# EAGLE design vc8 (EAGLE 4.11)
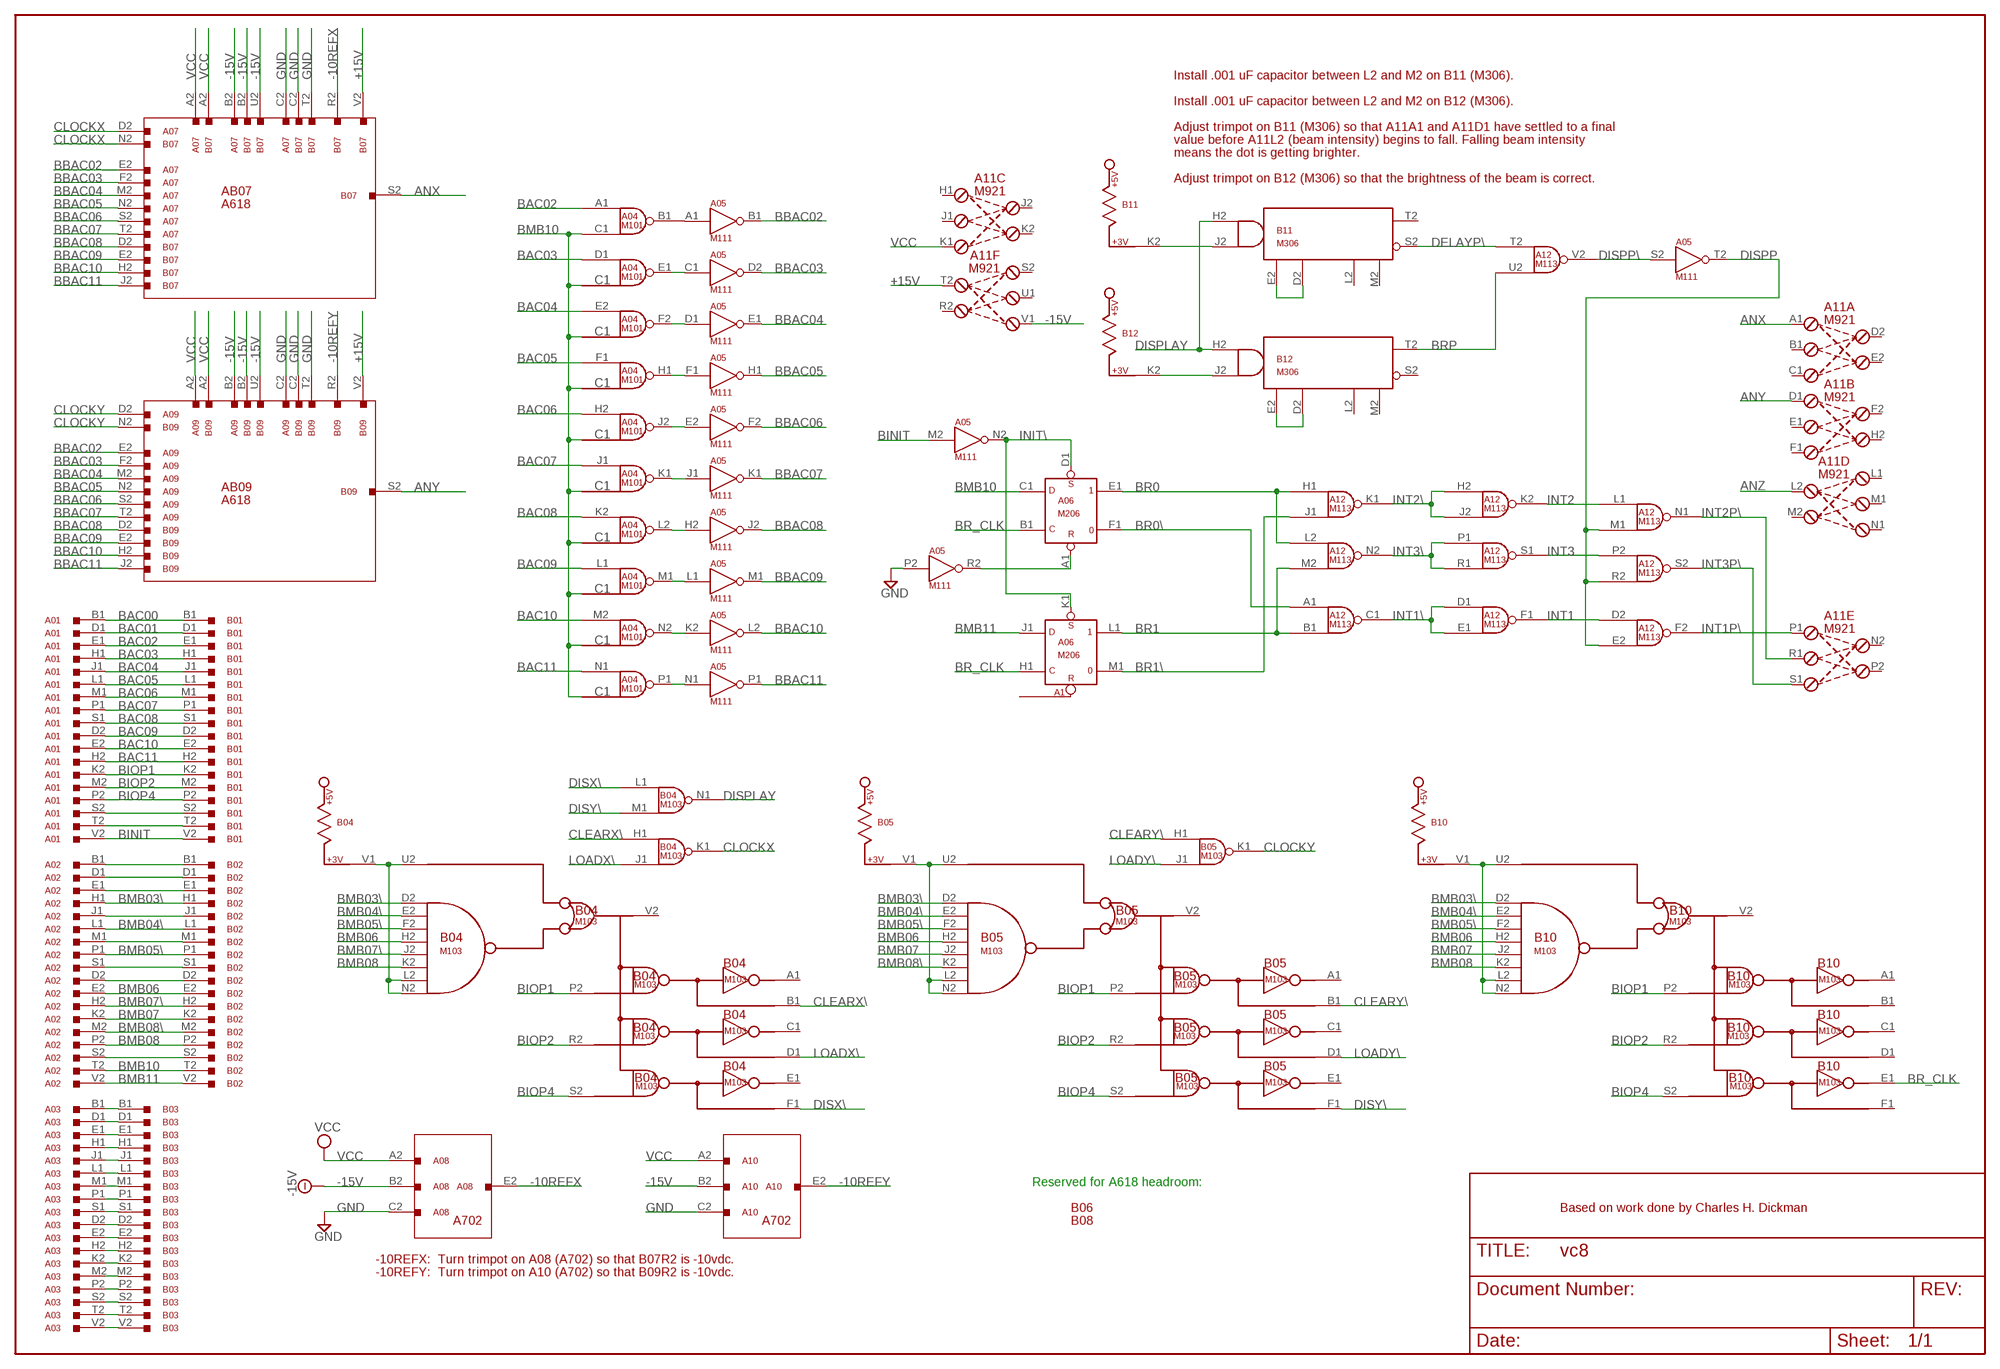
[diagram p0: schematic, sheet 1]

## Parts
A01  M903  [H807]
A02  M903  [H807]
A03  M903  [H807]
A04  M101  [H807]
A05  M111  [H807]
A06  M206  M206X  [H807]
A07  A618A  M916  [H807]
A08  A702  M916  [H807]
A09  A618A  M916  [H807]
A10  A702  M916  [H807]
A11  M921  [H807]
A12  M113  [H807]
B01  M903  [H807]
B02  M903  [H807]
B03  M903  [H807]
B04  M103  [H807]
B05  M103  [H807]
B06  EMPTY  [H807]
B07  A618B  M916  [H807]
B08  EMPTY  [H807]
B09  A618B  M916  [H807]
B10  M103  [H807]
B11  M306  [H807]
B12  M306  [H807]

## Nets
+3VB04: B04.L2(V2:L2) B04.N2(V2:N2) B04.U2(V2:U2) B04.V1
+3VB05: B05.L2(V2:L2) B05.N2(V2:N2) B05.U2(V2:U2) B05.V1
+3VB10: B10.L2(V2:L2) B10.N2(V2:N2) B10.U2(V2:U2) B10.V1
+15V: A11.T2(F:R1) B07.V2 B09.V2
-10REFX: A08.E2 B07.R2
-10REFY: A10.E2 B09.R2
-15V: A07.B2 A08.B2 A09.B2 A10.B2 A11.V1(F:L3) B07.B2 B07.U2 B09.B2 B09.U2
ANX: A11.A1(A:L1) B07.S2
ANY: A11.D1(B:L1) B09.S2
ANZ: A11.L2(D:R1)
BAC00: A01.B1 B01.B1
BAC01: A01.D1 B01.D1
BAC02: A01.E1 A04.A1(B1:IN1) B01.E1
BAC03: A01.H1 A04.D1(E1:IN) B01.H1
BAC04: A01.J1 A04.E2(F2:IN) B01.J1
BAC05: A01.L1 A04.F1(H1:IN) B01.L1
BAC06: A01.M1 A04.H2(J2:IN) B01.M1
BAC07: A01.P1 A04.J1(K1:IN) B01.P1
BAC08: A01.S1 A04.K2(L2:IN) B01.S1
BAC09: A01.D2 A04.L1(M1:IN) B01.D2
BAC10: A01.E2 A04.M2(N2:IN) B01.E2
BAC11: A01.H2 A04.N1(P1:IN) B01.H2
BBAC02: A05.B1(B1:OUT) A07.E2 A09.E2
BBAC03: A05.D2(D2:OUT) A07.F2 A09.F2
BBAC04: A05.E1(E1:OUT) A07.M2 A09.M2
BBAC05: A05.H1(H1:OUT) A07.N2 A09.N2
BBAC06: A05.F2(F2:OUT) A07.S2 A09.S2
BBAC07: A05.K1(K1:OUT) A07.T2 A09.T2
BBAC08: A05.J2(J2:OUT) B07.D2 B09.D2
BBAC09: A05.M1(M1:OUT) B07.E2 B09.E2
BBAC10: A05.L2(L2:OUT) B07.H2 B09.H2
BBAC11: A05.P1(P1:OUT) B07.J2 B09.J2
BINIT: A01.V2 A05.M2(N2:IN) B01.V2
BIOP1: A01.K2 B01.K2 B04.P2(V2:P2) B05.P2(V2:P2) B10.P2(V2:P2)
BIOP2: A01.M2 B01.M2 B04.R2(V2:R2) B05.R2(V2:R2) B10.R2(V2:R2)
BIOP4: A01.P2 B01.P2 B04.S2(V2:S2) B05.S2(V2:S2) B10.S2(V2:S2)
BMB03\: A02.H1 B02.H1 B04.D2(V2:D2) B05.D2(V2:D2) B10.D2(V2:D2)
BMB04\: A02.L1 B02.L1 B04.E2(V2:E2) B05.E2(V2:E2) B10.E2(V2:E2)
BMB05\: A02.P1 B02.P1 B04.F2(V2:F2) B05.F2(V2:F2) B10.F2(V2:F2)
BMB06: A02.E2 B02.E2 B04.H2(V2:H2) B05.H2(V2:H2) B10.H2(V2:H2)
BMB07: A02.K2 B02.K2 B05.J2(V2:J2) B10.J2(V2:J2)
BMB07\: A02.H2 B02.H2 B04.J2(V2:J2)
BMB08: A02.P2 B02.P2 B04.K2(V2:K2) B10.K2(V2:K2)
BMB08\: A02.M2 B02.M2 B05.K2(V2:K2)
BMB10: A02.T2 A04.C1(B1:IN2) A06.C1(E1:D) B02.T2
BMB11: A02.V2 A06.J1(L1:D) B02.V2
BR0: A06.E1 A12.H1(K1:IN1) A12.L2(N2:IN1)
BR0\: A06.F1 A12.A1(C1:IN1)
BR1: A06.L1 A12.B1(C1:IN2) A12.M2(N2:IN2)
BR1\: A06.M1 A12.J1(K1:IN2)
BR_CLK: A06.B1(E1:C) A06.H1(L1:C) B10.E1(V2:E1)
BRP: A12.U2(V2:IN2) B12.T2(T)
CLEARX\: B04.B1(V2:B1) B04.H1(K1:IN1)
CLEARY\: B05.B1(V2:B1) B05.H1(K1:IN1)
CLOCKX: A07.D2 B04.K1(K1:OUT) B07.N2
CLOCKY: A09.D2 B05.K1(K1:OUT) B09.N2
DELAYP\: A12.T2(V2:IN1) B11.S2(S)
DISPLAY: B04.N1(N1:OUT) B11.H2(H) B12.H2(H)
DISPP: A05.T2(T2:OUT) A12.E2(F2:IN2) A12.M1(N1:IN2) A12.R2(S2:IN2)
DISPP\: A05.S2(T2:IN) A12.V2(V2:OUT)
DISX\: B04.F1(V2:F1) B04.L1(N1:IN1)
DISY\: B04.M1(N1:IN2) B05.F1(V2:F1)
GND: A05.P2(R2:IN) A07.C2 A08.C2 A09.C2 A10.C2 B07.C2 B07.T2 B09.C2 B09.T2
INIT\: A05.N2(N2:OUT) A06.D1(E1:S) A06.K1(L1:S)
INT1: A12.D2(F2:IN1) A12.F1(F1:OUT)
INT1\: A12.C1(C1:OUT) A12.D1(F1:IN1) A12.E1(F1:IN2)
INT1P\: A11.P1(E:L1) A12.F2(F2:OUT)
INT2: A12.K2(K2:OUT) A12.L1(N1:IN1)
INT2\: A12.H2(K2:IN1) A12.J2(K2:IN2) A12.K1(K1:OUT)
INT2P\: A11.R1(E:L2) A12.N1(N1:OUT)
INT3: A12.P2(S2:IN1) A12.S1(S1:OUT)
INT3\: A12.N2(N2:OUT) A12.P1(S1:IN1) A12.R1(S1:IN2)
INT3P\: A11.S1(E:L3) A12.S2(S2:OUT)
LOADX\: B04.D1(V2:D1) B04.J1(K1:IN2)
LOADY\: B05.D1(V2:D1) B05.J1(K1:IN2)
N$1: A05.R2(R2:OUT) A06.A1(E1:R)
N$2: B11.J2(J) B11.K2
N$4: B12.J2(J) B12.K2
N$6: B11.D2(D) B11.E2(E)
N$7: B12.D2(D) B12.E2(E)
N$9: A04.B1(B1:OUT) A05.A1(B1:IN)
N$10: A04.E1(E1:OUT) A05.C1(D2:IN)
N$11: A04.F2(F2:OUT) A05.D1(E1:IN)
N$12: A04.H1(H1:OUT) A05.F1(H1:IN)
N$13: A04.J2(J2:OUT) A05.E2(F2:IN)
N$14: A04.P1(P1:OUT) A05.N1(P1:IN)
N$15: A04.N2(N2:OUT) A05.K2(L2:IN)
N$16: A04.M1(M1:OUT) A05.L1(M1:IN)
N$17: A04.L2(L2:OUT) A05.H2(J2:IN)
N$18: A04.K1(K1:OUT) A05.J1(K1:IN)
N$21: A03.B1 B03.B1
N$22: A03.D1 B03.D1
N$23: A03.E1 B03.E1
N$24: A03.H1 B03.H1
N$26: A03.J1 B03.J1
N$27: A03.L1 B03.L1
N$28: A03.M1 B03.M1
N$29: A03.P1 B03.P1
N$30: A03.S1 B03.S1
N$33: A03.D2 B03.D2
N$34: A03.E2 B03.E2
N$35: A03.H2 B03.H2
N$36: A03.K2 B03.K2
N$37: A03.M2 B03.M2
N$38: A03.P2 B03.P2
N$39: A03.S2 B03.S2
N$40: A03.T2 B03.T2
N$41: A03.V2 B03.V2
N$42: A02.D2 B02.D2
N$43: A02.S1 B02.S1
N$44: A02.J1 B02.J1
N$45: A02.M1 B02.M1
N$46: A02.S2 B02.S2
N$47: A02.B1 B02.B1
N$48: A02.D1 B02.D1
N$49: A02.E1 B02.E1
N$50: A01.T2 B01.T2
N$51: A01.S2 B01.S2
VCC: A07.A2 A08.A2 A09.A2 A10.A2 A11.K1(C:L3) B07.A2 B09.A2
Unconnected: A04.P2(R2:IN) A04.R1(S1:IN) A04.R2(R2:OUT) A04.S1(S1:OUT) A04.S2(T2:IN) A04.T2(T2:OUT) A04.U1(U1:OUT) A04.U2(V2:IN) A04.V1(U1:IN) A04.V2(V2:OUT) A05.R1(S1:IN) A05.S1(S1:OUT) A05.U1(U1:OUT) A05.U2(V2:IN) A05.V1(U1:IN) A05.V2(V2:OUT) A06.D2(H2:C) A06.E2(H2:D) A06.F2(H2:S) A06.H2 A06.J2 A06.K2(P2:R) A06.L2(P2:C) A06.M2(P2:D) A06.N1(S1:C) A06.N2(P2:S) A06.P1(S1:D) A06.P2 A06.R1(S1:S) A06.R2 A06.S1 A06.S2(V2:C) A06.T2(V2:D) A06.U1 A06.U2(V2:S) A06.V1 A06.V2 A07.A1 A07.B1 A07.C1 A07.D1 A07.E1 A07.F1 A07.H1 A07.H2 A07.J1 A07.J2 A07.K1 A07.K2 A07.L1 A07.L2 A07.M1 A07.N1 A07.P1 A07.P2 A07.R1 A07.R2 A07.S1 A07.T1 A07.U1 A07.U2 A07.V1 A07.V2 A08.A1 A08.B1 A08.C1 A08.D1 A08.D2 A08.E1 A08.F1 A08.F2 A08.H1 A08.H2 A08.J1 A08.J2 A08.K1 A08.K2 A08.L1 A08.L2 A08.M1 A08.M2 A08.N1 A08.N2 A08.P1 A08.P2 A08.R1 A08.R2 A08.S1 A08.S2 A08.T1 A08.T2 A08.U1 A08.U2 A08.V1 A08.V2 A09.A1 A09.B1 A09.C1 A09.D1 A09.E1 A09.F1 A09.H1 A09.H2 A09.J1 A09.J2 A09.K1 A09.K2 A09.L1 A09.L2 A09.M1 A09.N1 A09.P1 A09.P2 A09.R1 A09.R2 A09.S1 A09.T1 A09.U1 A09.U2 A09.V1 A09.V2 A10.A1 A10.B1 A10.C1 A10.D1 A10.D2 A10.E1 A10.F1 A10.F2 A10.H1 A10.H2 A10.J1 A10.J2 A10.K1 A10.K2 A10.L1 A10.L2 A10.M1 A10.M2 A10.N1 A10.N2 A10.P1 A10.P2 A10.R1 A10.R2 A10.S1 A10.S2 A10.T1 A10.T2 A10.U1 A10.U2 A10.V1 A10.V2 A11.B1(A:L2) A11.C1(A:L3) A11.D2(A:R1) A11.E1(B:L2) A11.E2(A:R2) A11.F1(B:L3) A11.F2(B:R1) A11.H1(C:L1) A11.H2(B:R2) A11.J1(C:L2) A11.J2(C:R1) A11.K2(C:R2) A11.L1(D:L1) A11.M1(D:L2) A11.M2(D:R2) A11.N1(D:L3) A11.N2(E:R1) A11.P2(E:R2) A11.R2(F:R2) A11.S2(F:L1) A11.U1(F:L2) A12.U1 A12.V1 B04.A1(V2:A1) B04.C1(V2:C1) B04.E1(V2:E1) B04.V2(V2:V2) B05.A1(V2:A1) B05.C1(V2:C1) B05.E1(V2:E1) B05.L1(N1:IN1) B05.M1(N1:IN2) B05.N1(N1:OUT) B05.V2(V2:V2) B07.A1 B07.B1 B07.C1 B07.D1 B07.E1 B07.F1 B07.F2 B07.H1 B07.J1 B07.K1 B07.K2 B07.L1 B07.L2 B07.M1 B07.M2 B07.N1 B07.P1 B07.P2 B07.R1 B07.S1 B07.T1 B07.U1 B07.V1 B09.A1 B09.B1 B09.C1 B09.D1 B09.E1 B09.F1 B09.F2 B09.H1 B09.J1 B09.K1 B09.K2 B09.L1 B09.L2 B09.M1 B09.M2 B09.N1 B09.P1 B09.P2 B09.R1 B09.S1 B09.T1 B09.U1 B09.V1 B10.A1(V2:A1) B10.B1(V2:B1) B10.C1(V2:C1) B10.D1(V2:D1) B10.F1(V2:F1) B10.H1(K1:IN1) B10.J1(K1:IN2) B10.K1(K1:OUT) B10.L1(N1:IN1) B10.M1(N1:IN2) B10.N1(N1:OUT) B10.V2(V2:V2) B11.L2(L) B11.M2(M) B11.T2(T) B12.L2(L) B12.M2(M) B12.S2(S)

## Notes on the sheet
- Install .001 uF capacitor between L2 and M2 on B11 (M306).
- Install .001 uF capacitor between L2 and M2 on B12 (M306).
- Adjust trimpot on B11 (M306) so that A11A1 and A11D1 have settled to a final
- value before A11L2 (beam intensity) begins to fall. Falling beam intensity
- means the dot is getting brighter.
- Adjust trimpot on B12 (M306) so that the brightness of the beam is correct.
- AB07
- A618
- AB09
- A618
- Reserved for A618 headroom:
- Based on work done by Charles H. Dickman
- A702 | A702
- -10REFX:  Turn trimpot on A08 (A702) so that B07R2 is -10vdc.
- -10REFY:  Turn trimpot on A10 (A702) so that B09R2 is -10vdc.

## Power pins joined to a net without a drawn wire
-15V: B06.B2 B08.B2
GND: A01.A1 A01.C1 A01.C2 A01.F1 A01.F2 A01.J2 A01.K1 A01.L2 A01.N1 A01.N2 A01.R1 A01.R2 A01.T1 A01.U2 A02.A1 A02.C1 A02.C2 A02.F1 A02.F2 A02.J2 A02.K1 A02.L2 A02.N1 A02.N2 A02.R1 A02.R2 A02.T1 A02.U2 A03.A1 A03.C1 A03.C2 A03.F1 A03.F2 A03.J2 A03.K1 A03.L2 A03.N1 A03.N2 A03.R1 A03.R2 A03.T1 A03.U2 A04.C2(GND) A04.T1(GND) A05.C2(GND) A05.T1(GND) A06.C2(GND) A06.T1(GND) A12.C2(GND) A12.T1(GND) B01.A1 B01.C1 B01.C2 B01.F1 B01.F2 B01.J2 B01.K1 B01.L2 B01.N1 B01.N2 B01.R1 B01.R2 B01.T1 B01.U2 B02.A1 B02.C1 B02.C2 B02.F1 B02.F2 B02.J2 B02.K1 B02.L2 B02.N1 B02.N2 B02.R1 B02.R2 B02.T1 B02.U2 B03.A1 B03.C1 B03.C2 B03.F1 B03.F2 B03.J2 B03.K1 B03.L2 B03.N1 B03.N2 B03.R1 B03.R2 B03.T1 B03.U2 B04.C2(GND) B04.T1(GND) B05.C2(GND) B05.T1(GND) B06.C2 B08.C2 B10.C2(GND) B10.T1(GND) B11.C2(GND) B12.C2(GND)
VCC: A04.A2(VCC) A05.A2(VCC) A06.A2(VCC) A12.A2(VCC) B04.A2(VCC) B05.A2(VCC) B06.A2 B08.A2 B10.A2(VCC) B11.A2(VCC) B12.A2(VCC)

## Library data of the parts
A01-A03 B01-B03 = dec-m:M903: Two-sided Posibus cable/connector.
A04 = dec-r:M101: Bus Data Interface The M101 contains 15 two-input NAND gates. One input of each gate is tied to a common line so that all data signals can be enabled simultaneously. Each data signal presents one TTL load. The common input presents 15 loads. Each output can drive 10 loads. Power: 5V@82ma (max.)
A05 = dec-r:M111: Sixteen inverters.
A06 = dec-r:M206X: Two sets of 3 D flip-flops
A07-A09 A10 B07 B09 = dec-r:M916: Simple 36 pin connector/wire cable
A11 = dec-r:M921: Device Code Select Jumper Board
A12 = dec-r:M113: 10 2-input NAND Gates
B04 B05 B10 = dec-r:M103: M103 Device Selector Used to decode IOT requests.
B06 B08 = dec-r:EMPTY: Empty Slot
B11 B12 = dec-r:M306: M306 Integrating One-Shot

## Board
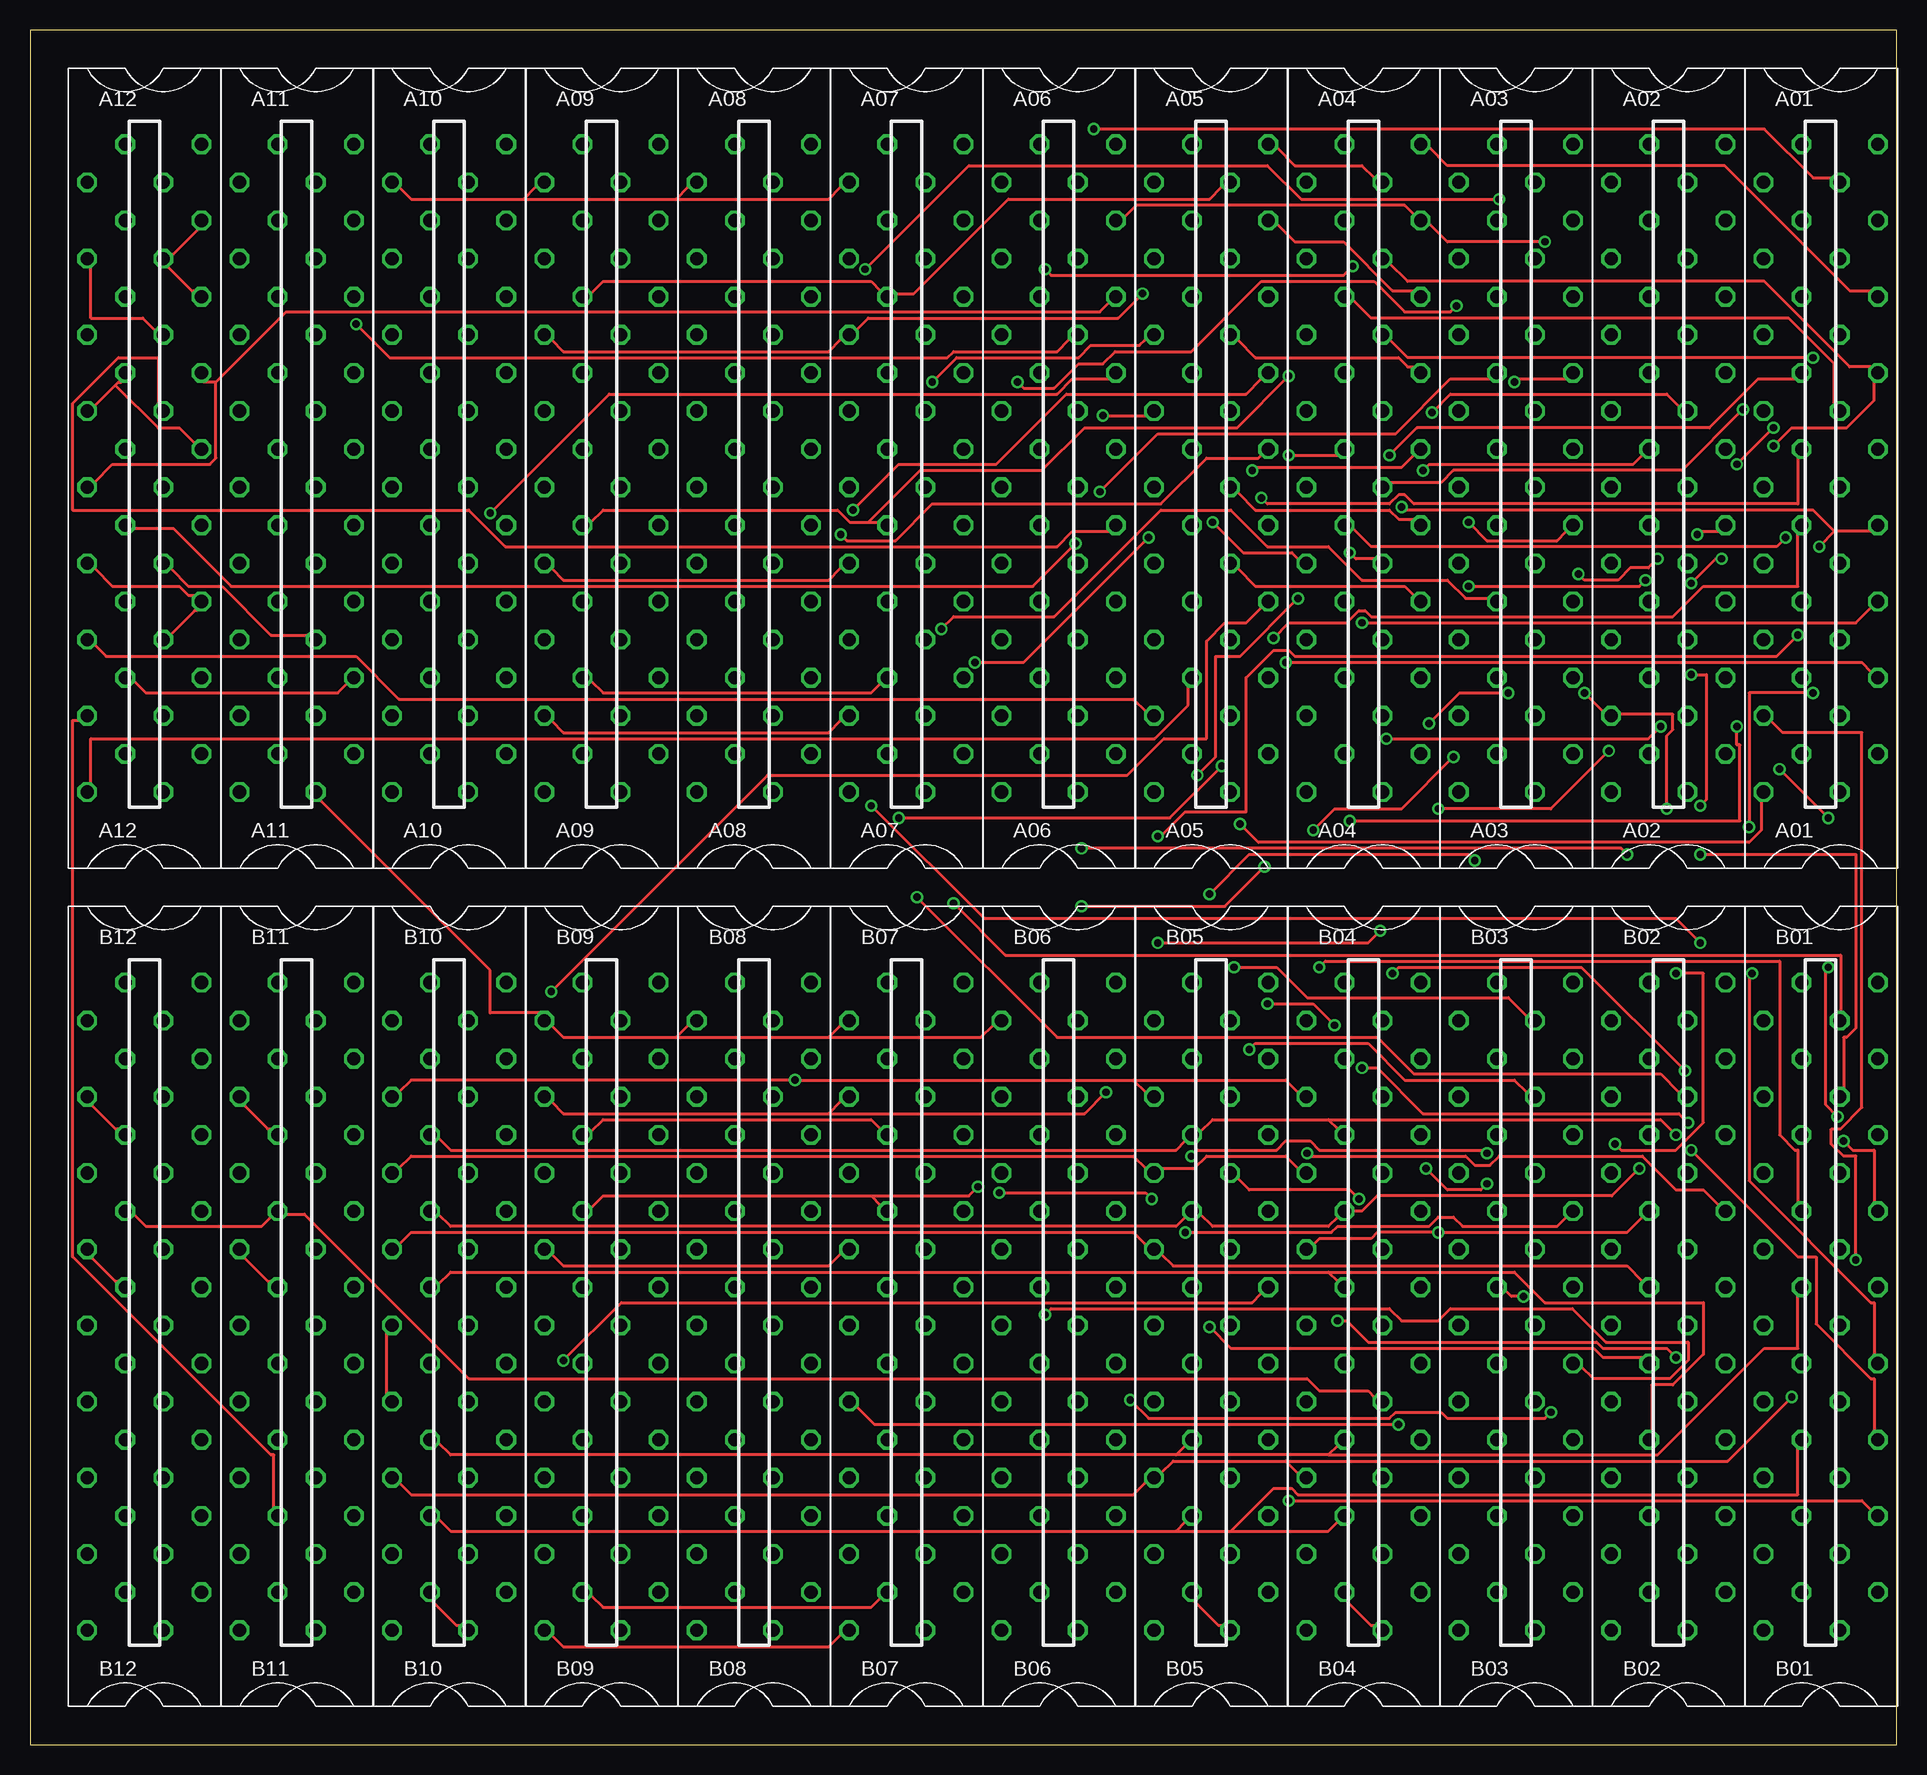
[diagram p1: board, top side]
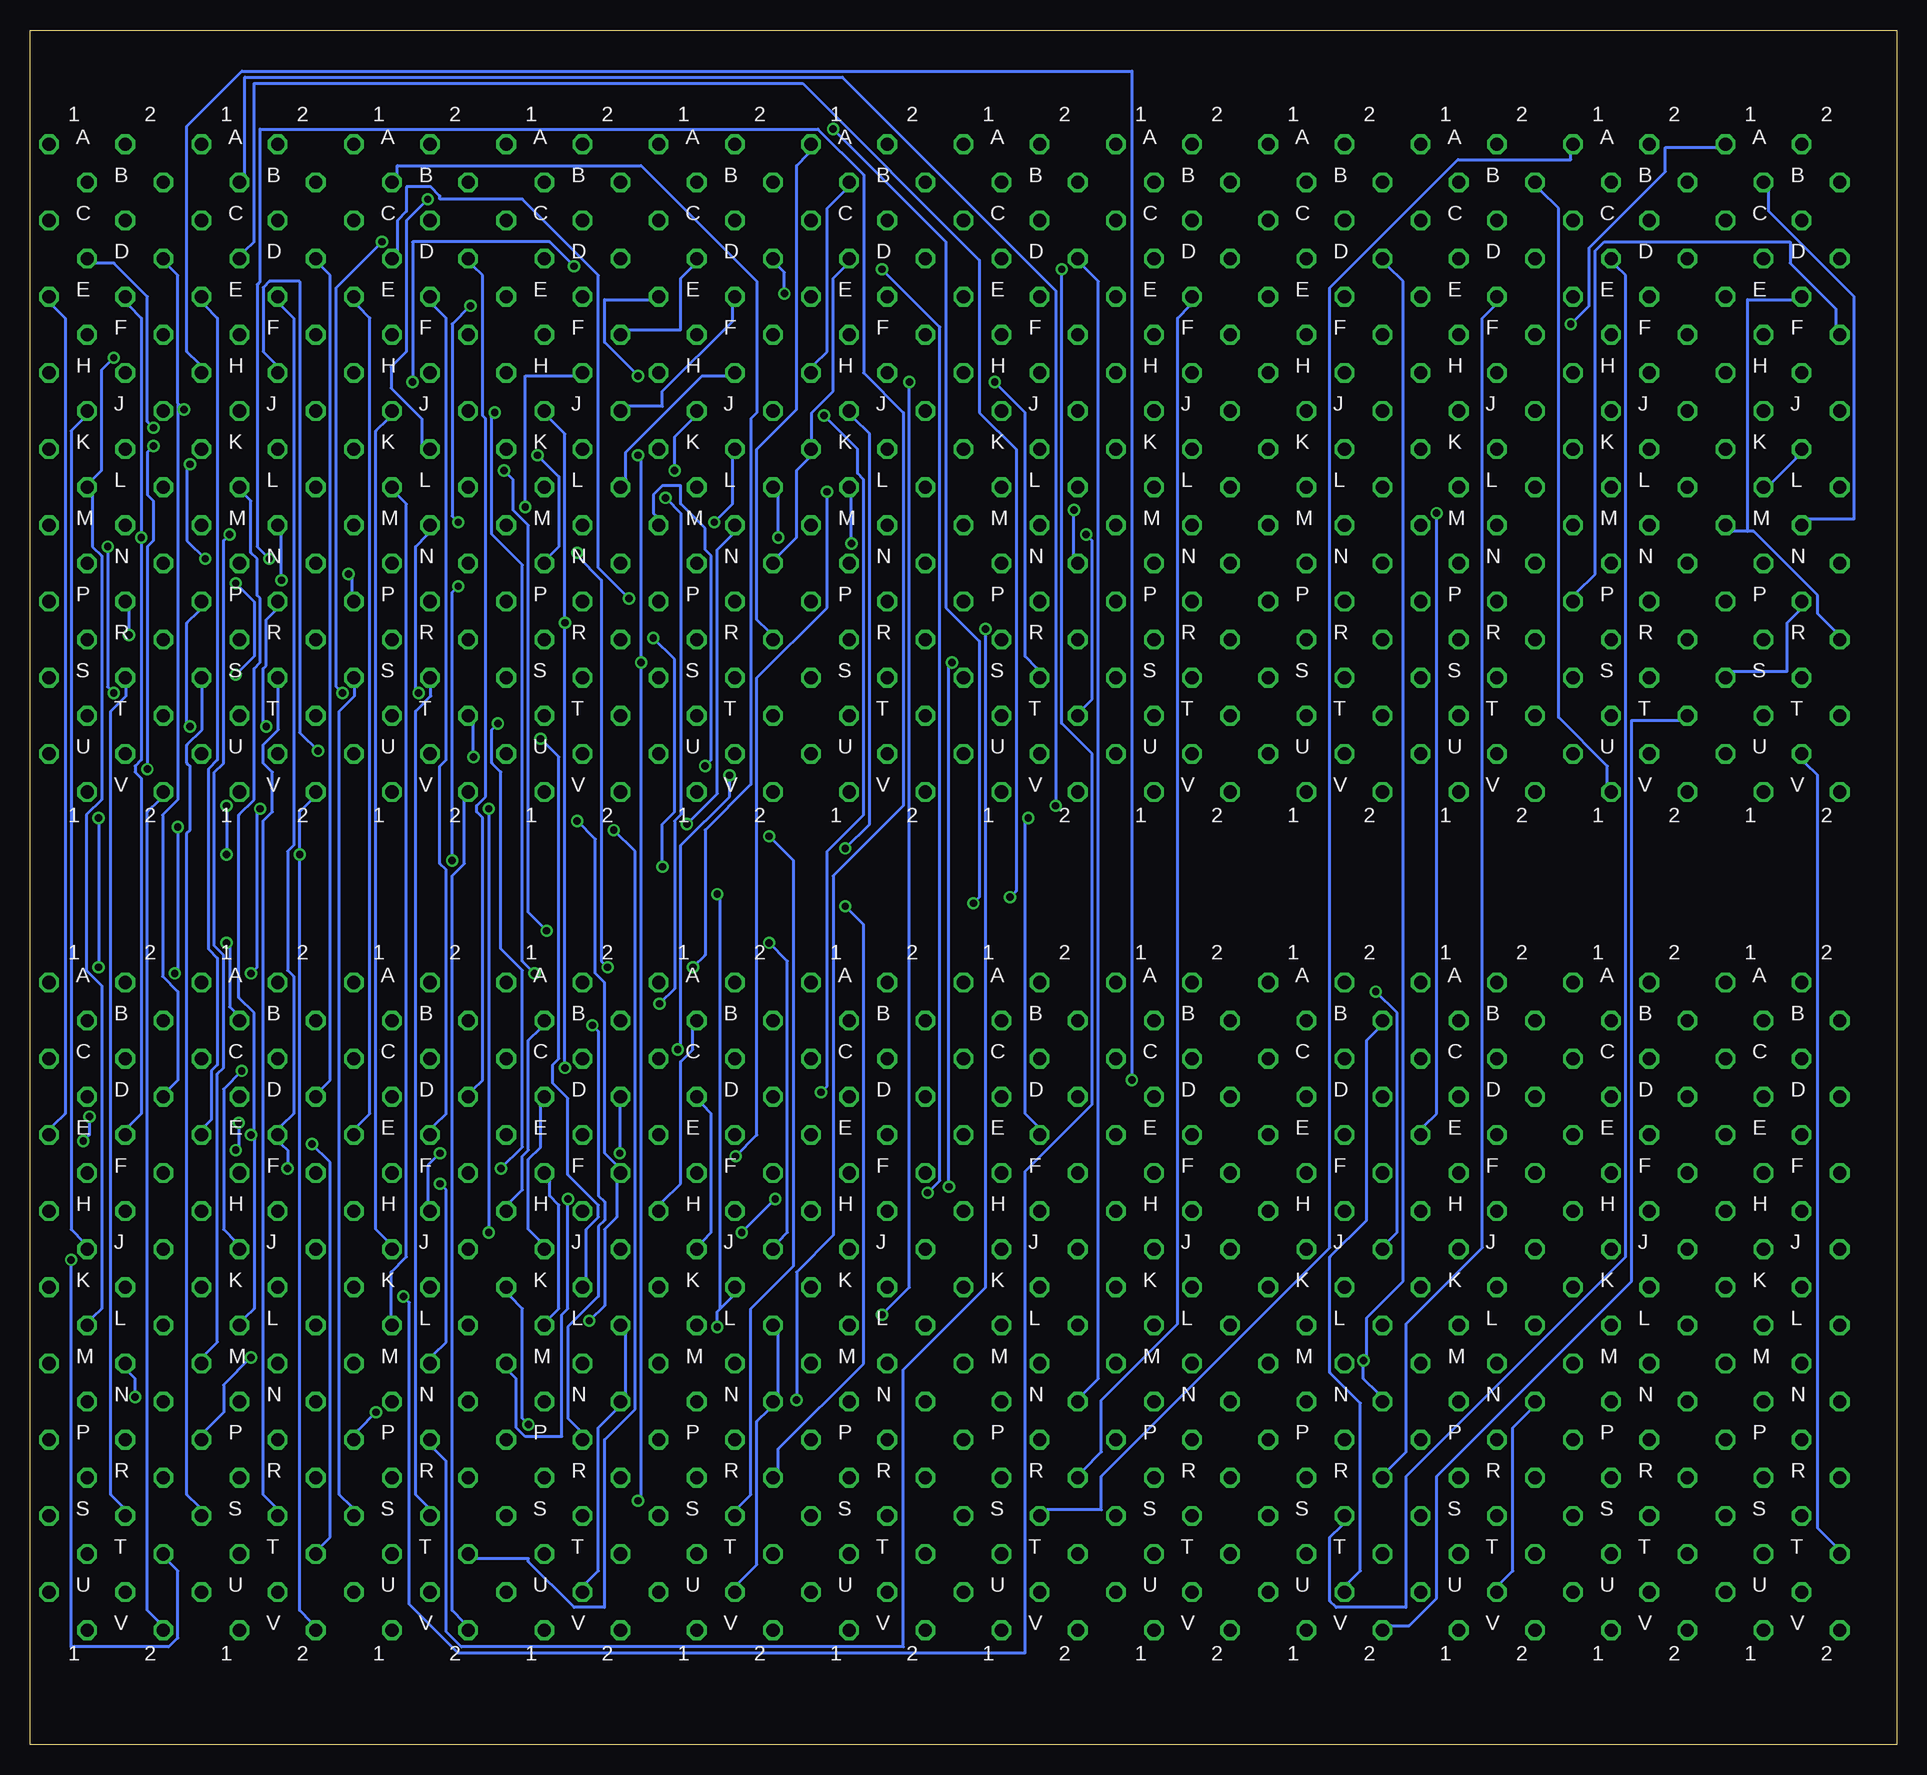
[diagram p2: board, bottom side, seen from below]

Size 155.57 x 142.88 mm. Coordinates in mm from the lower left corner, seen from the top.
Outline: 0,0 155.57,0 155.57,142.88 0,142.88 0,0
Copper layers (1*16): Top 0.035mm / dielectric 1.5mm / Bottom 0.035mm
Design rules "custompcb": minimum track width 10mil, minimum drill 24mil, track to track 8mil, track to pad 8mil, pad to pad 8mil, via to via 8mil, smd to smd 0mil, copper to edge 25mil, drill to drill 8mil, minimum pad ring 10mil, minimum via ring 8mil, stop-mask expansion 4mil, vias tented up to drill 0mil, thermal gap 10mil

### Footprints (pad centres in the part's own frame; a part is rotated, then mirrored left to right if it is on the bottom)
H807 = drill 1.092 octagon: A1 4.763,28.575; A2 -1.587,28.575; B1 1.587,25.4; B2 -4.763,25.4; C1 4.763,22.225; C2 -1.587,22.225; D1 1.587,19.05; D2 -4.763,19.05; E1 4.763,15.875; E2 -1.587,15.875; F1 1.587,12.7; F2 -4.763,12.7; H1 4.763,9.525; H2 -1.587,9.525; J1 1.587,6.35; J2 -4.763,6.35; K1 4.763,3.175; K2 -1.587,3.175; L1 1.587,0; L2 -4.763,0; M1 4.763,-3.175; M2 -1.587,-3.175; N1 1.587,-6.35; N2 -4.763,-6.35; P1 4.763,-9.525; P2 -1.587,-9.525; R1 1.587,-12.7; R2 -4.763,-12.7; S1 4.763,-15.875; S2 -1.587,-15.875; T1 1.587,-19.05; T2 -4.763,-19.05; U1 4.763,-22.225; U2 -1.587,-22.225; V1 1.587,-25.4; V2 -4.763,-25.4

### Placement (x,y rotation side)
A01  149.22,104.78 0 top
A02  136.53,104.78 0 top
A03  123.83,104.78 0 top
A04  111.12,104.78 0 top
A05  98.42,104.78 0 top
A06  85.72,104.78 0 top
A07  73.03,104.78 0 top
A08  60.33,104.78 0 top
A09  47.62,104.78 0 top
A10  34.92,104.78 0 top
A11  22.23,104.78 0 top
A12  9.53,104.78 0 top
B01  149.22,34.92 0 top
B02  136.53,34.92 0 top
B03  123.83,34.92 0 top
B04  111.12,34.92 0 top
B05  98.42,34.92 0 top
B06  85.72,34.92 0 top
B07  73.03,34.92 0 top
B08  60.33,34.92 0 top
B09  47.62,34.92 0 top
B10  34.92,34.92 0 top
B11  22.23,34.92 0 top
B12  9.53,34.92 0 top

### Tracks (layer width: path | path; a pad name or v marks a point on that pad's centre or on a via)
+3VB04
  Top 0.254: B04.U2 109.73,11.94 111.76,9.91 112.01,9.91 B04.V1
  Bottom 0.254: B04.L2 105.92,34.29 105.92,29.21 B04.N2 106.68,27.94 108.2,26.42 108.2,14.48 109.22,13.46 B04.U2
+3VB05
  Top 0.254: B05.U2 97.03,11.94 99.06,9.91 99.31,9.91 B05.V1
  Bottom 0.254: B05.L2 93.22,34.29 93.22,29.21 B05.N2 93.98,27.94 95,26.92 95,14.99 96.52,13.46 B05.U2
+3VB10
  Top 0.254: B10.N2 29.72,29.21 29.72,34.29 B10.L2 | B10.U2 33.53,11.94 35.56,9.91 35.81,9.91 B10.V1
  Bottom 0.254: B10.N2 30.48,27.94 32,26.42 32,14.48 33.02,13.46 B10.U2
+15V
  Top 0.254: B09.V2 43.43,9.14 44.45,8.13 66.55,8.13 67.56,9.14 B07.V2
  Bottom 0.254: A11.T2 18.03,85.34 22.1,85.34 22.1,38.61 38.35,22.35 38.35,12.19 40.64,9.91 42.16,9.91 B09.V2
-10REFX
  Bottom 0.254: B07.R2 67.82,22.86 66.29,24.38 66.29,28.7 59.94,35.05 59.94,118.87 58.93,119.89 A08.E2
-10REFY
  Bottom 0.254: B09.R2 42.42,22.86 40.89,24.38 40.89,35.05 34.54,41.4 34.54,118.87 33.53,119.89 A10.E2
-15V
  Top 0.254: 41.15,128.78 31.75,128.78 30.73,129.79 A10.B2 | 41.15,128.78 42.16,129.79 A09.B2 | 53.85,128.78 54.86,129.79 A08.B2 | 41.15,128.78 53.85,128.78 | 53.85,128.78 66.55,128.78 67.56,129.79 A07.B2 | B09.U2 46.74,12.45 47.75,11.43 70.1,11.43 70.87,12.19 B07.U2 | 53.85,58.93 44.45,58.93 43.43,59.94 B09.B2 42.42,60.96 38.35,60.96 38.35,64.52 24.13,78.74 A11.V1 | 53.85,58.93 54.86,59.94 B08.B2 | 66.55,58.93 67.56,59.94 B07.B2 | 53.85,58.93 66.55,58.93 | 66.55,58.93 79.25,58.93 80.26,59.94 B06.B2
  Bottom 0.254: B09.U2 45.72,13.46 44.7,14.48 44.7,28.45 47.24,30.99 47.24,40.64 44.2,43.69 44.2,58.67 43.18,59.69 B09.B2 | A10.B2 29.72,129.54 28.19,128.02 28.19,85.6 24.13,81.53 24.13,80.01 A11.V1
ANX
  Bottom 0.254: B07.S2 70.87,19.56 66.29,19.56 66.29,22.35 47.24,41.4 47.24,121.41 36.58,132.08 27.18,132.08 27.18,132.59 A11.A1
ANY
  Bottom 0.254: B09.S2 46.23,18.29 47.24,17.27 47.24,11.94 46.74,11.43 40.89,11.43 40.89,22.35 22.61,40.64 22.61,122.43 23.37,123.19 A11.D1
BAC00  (via drill 0.61)
  Top 0.254: v76.96,70.1 81.28,65.79 150.88,65.79 150.88,60.96 B01.B1 | v88.65,134.62 144.53,134.62 148.59,130.56 150.11,130.56 A01.B1
  Bottom 0.254: v76.96,70.1 76.45,70.61 76.45,91.95 79.25,94.74 79.25,125.22 v88.65,134.62
BAC01  (via drill 0.61)
  Top 0.254: v139.19,74.17 152.15,74.17 152.15,59.69 151.38,58.93 151.13,58.93 151.13,54.61 B01.D1 | v139.19,78.23 139.7,78.74 139.7,89.15 v138.43,89.15 | v138.43,96.77 140.46,98.81 v140.97,98.81 | v145.29,109.73 v142.24,106.68
  Bottom 0.254: v139.19,78.23 v139.19,74.17 | v138.43,89.15 136.91,90.68 136.91,95.25 v138.43,96.77 | v140.97,98.81 142.49,100.33 142.49,106.43 v142.24,106.68 | v145.29,109.73 145.8,110.24 145.8,120.65 148.59,123.44 150.11,123.44 A01.D1
BAC02
  Top 0.254: A04.A1 116.59,133.1 118.11,131.57 141.22,131.57 151.64,121.16 153.42,121.16 A01.E1
  Bottom 0.254: B01.E1 153.67,51.56 152.65,52.58 152.65,118.87 153.67,119.89 A01.E1
BAC03  (via drill 0.61)
  Top 0.254: v151.13,50.29 151.89,49.53 153.67,49.53 153.67,45.21 B01.H1 | v150.62,52.32 149.61,53.34 149.61,64.77 v149.86,64.77 | v145.8,81.28 v149.86,77.22 | v145.29,108.2 146.81,109.73 151.38,109.73 153.67,112.01 153.67,113.54 A01.H1 153.42,114.81 151.64,114.81 144.53,121.92 114.81,121.92 113.28,123.44 A04.D1
  Bottom 0.254: v151.13,50.29 150.62,50.8 v150.62,52.32 | v149.86,77.22 v149.86,64.77 | v145.8,81.28 145.8,99.82 145.29,100.33 145.29,103.63 145.8,104.14 145.8,107.7 v145.29,108.2
BAC04
  Top 0.254: A04.E2 110.24,120.4 111.76,118.87 146.56,118.87 150.37,115.06 150.37,111.76 A01.J1
  Bottom 0.254: B01.J1 151.13,41.91 152.15,42.93 152.15,109.47 151.13,110.49 A01.J1
BAC05  (via drill 0.61)
  Top 0.254: v148.59,115.57 114.81,115.57 113.28,117.09 A04.F1
  Bottom 0.254: B01.L1 150.37,35.56 149.61,36.32 149.61,63.25 150.88,64.52 150.88,77.47 149.61,78.74 149.61,99.06 150.37,99.82 150.37,104.14 A01.L1 150.37,105.41 149.61,106.17 149.61,114.55 v148.59,115.57
BAC06  (via drill 0.61)
  Top 0.254: v143.51,64.26 143.26,64.26 143.26,46.99 153.42,36.83 153.67,36.83 153.67,32.51 B01.M1 | v143.26,76.45 143.26,87.63 v148.59,87.63 | 150.37,101.09 v149.1,99.82 | 150.37,101.09 153.42,101.09 A01.M1 | v114.3,103.12 114.55,102.87 148.59,102.87 150.37,101.09
  Bottom 0.254: v143.51,64.26 143.26,64.52 v143.26,76.45 | v148.59,87.63 149.1,88.14 v149.1,99.82 | v114.3,103.12 114.3,114.05 110.24,114.05 A04.H2
BAC07  (via drill 0.61)
  Top 0.254: v138.43,49.53 147.32,40.64 148.84,40.64 148.84,35.05 153.42,30.48 153.67,30.48 153.67,26.16 B01.P1 | v138.18,51.82 137.41,52.58 116.08,52.58 112.27,56.39 v111,56.39 | v111,93.47 152.15,93.47 153.42,94.74 A01.P1
  Bottom 0.254: v138.43,49.53 138.18,49.78 v138.18,51.82 | v111,56.39 v111,93.47 111,109.22 112.27,110.49 A04.J1
BAC08  (via drill 0.61)
  Top 0.254: v104.9,20.32 152.65,20.32 153.42,19.56 B01.S1 | v104.9,107.44 108.97,107.44 A04.K2 | v104.65,90.17 152.65,90.17 153.42,89.41 A01.S1
  Bottom 0.254: v104.9,20.32 104.65,20.57 v104.65,90.17 104.65,107.19 v104.9,107.44
BAC09  (via drill 0.61)
  Top 0.254: v142.75,111.25 137.67,106.17 118.62,106.17 117.6,105.16 113.28,105.16 A04.L1
  Bottom 0.254: 143.26,111.76 v142.75,111.25 | 143.26,111.76 143.26,122.43 144.02,123.19 A01.D2 | 143.26,111.76 143.26,78.74 144.53,77.47 144.53,64.01 143.26,62.74 143.26,55.37 144.02,54.61 B01.D2
BAC10  (via drill 0.61)
  Top 0.254: v146.3,100.58 145.54,99.82 111.76,99.82 110.24,101.35 A04.M2
  Bottom 0.254: A01.E2 147.32,119.89 146.3,118.87 v146.3,100.58 146.3,100.33 146.3,82.04 146.81,81.53 146.81,81.03 146.3,80.52 146.3,52.58 147.32,51.56 B01.E2
BAC11  (via drill 0.61)
  Top 0.254: v113.28,107.44 115.57,109.73 139.95,109.73 144.02,113.79 147.07,113.79 A01.H2 | v107.44,64.77 107.95,65.28 145.8,65.28 145.8,50.8 147.07,49.53 147.32,49.53 147.32,45.21 B01.H2 | v109.98,99.31 110.49,98.81 112.01,98.81 A04.N1
  Bottom 0.254: v113.28,107.44 111.51,105.66 111.51,99.82 112.27,99.06 A04.N1 | v107.44,64.77 107.95,65.28 107.95,97.03 109.98,99.06 v109.98,99.31
BBAC02
  Top 0.254: A09.E2 46.74,120.9 47.75,121.92 70.1,121.92 70.87,121.16 A07.E2 72.14,120.9 73.66,120.9 81.53,128.78 98.3,128.78 99.31,129.79 A05.B1
BBAC03  (via drill 0.61)
  Top 0.254: A09.F2 43.43,117.09 44.45,116.08 66.55,116.08 67.56,117.09 A07.F2 68.83,117.86 69.85,118.87 90.68,118.87 v92.71,120.9
  Bottom 0.254: v92.71,120.9 92.71,122.68 93.22,123.19 A05.D2
BBAC04  (via drill 0.61)
  Top 0.254: 69.85,101.85 70.87,101.85 A07.M2 | 69.85,101.85 68.33,101.85 67.31,102.87 47.75,102.87 46.74,101.85 A09.M2 | v104.9,114.05 100.58,109.73 87.88,109.73 84.33,106.17 74.17,106.17 69.85,101.85
  Bottom 0.254: v104.9,114.05 107.7,116.84 107.7,120.4 103.89,120.4 A05.E1
BBAC05  (via drill 0.61)
  Top 0.254: A09.N2 43.43,98.04 44.45,97.03 66.55,97.03 67.56,98.04 A07.N2 | v68.58,102.87 72.39,106.68 80.52,106.68 86.36,112.52 101.35,112.52 102.62,113.79 A05.H1
  Bottom 0.254: v68.58,102.87 68.58,99.06 A07.N2
BBAC06  (via drill 0.61)
  Top 0.254: A09.S2 46.74,88.65 47.75,87.63 70.1,87.63 70.87,88.39 A07.S2 | v75.18,113.54 77.22,115.57 87.38,115.57 88.39,116.59 92.46,116.59 92.96,117.09 A05.F2
  Bottom 0.254: v75.18,113.54 72.64,111 72.64,90.68 71.63,89.66 A07.S2
BBAC07  (via drill 0.61)
  Top 0.254: A09.T2 43.43,85.34 44.45,84.33 66.55,84.33 67.56,85.34 A07.T2 | v67.56,100.84 68.07,100.33 72.14,100.33 75.18,103.38 94.23,103.38 98.04,107.19 102.36,107.19 102.62,107.44 A05.K1
  Bottom 0.254: v67.56,100.84 67.06,100.33 67.06,87.12 67.82,86.36 A07.T2
BBAC08  (via drill 0.61)
  Top 0.254: 66.55,52.58 44.45,52.58 43.43,53.59 B09.D2 | 66.55,52.58 67.56,53.59 B07.D2 | v89.41,110.74 92.96,110.74 A05.J2 | v89.66,54.36 87.88,52.58 66.55,52.58
  Bottom 0.254: v89.41,110.74 86.61,107.95 86.61,105.92 86.11,105.41 86.11,77.47 89.15,74.42 89.15,54.86 v89.66,54.36
BBAC09  (via drill 0.61)
  Top 0.254: B09.E2 46.74,51.05 47.75,52.07 70.1,52.07 70.87,51.31 B07.E2 | v99.31,81.53 95,77.22 v72.39,77.22
  Bottom 0.254: v99.31,81.53 98.81,82.04 98.81,99.06 99.31,99.57 99.31,101.35 101.35,103.38 101.35,104.9 102.87,104.9 103.63,104.14 103.63,102.62 103.38,102.36 A05.M1 | v72.39,77.22 72.64,76.96 72.64,52.58 71.63,51.56 B07.E2
BBAC10  (via drill 0.61)
  Top 0.254: 70.1,45.72 47.75,45.72 46.74,44.7 B09.H2 | 70.1,45.72 70.87,44.96 B07.H2 | v93.22,100.58 82.8,90.17 v78.74,90.17 | v78.99,46.48 78.23,45.72 70.1,45.72
  Bottom 0.254: v93.22,100.58 93.22,104.14 A05.L2 | v78.74,90.17 78.99,89.92 v78.99,46.48
BBAC11  (via drill 0.61)
  Top 0.254: B09.J2 43.43,40.89 44.45,39.88 66.55,39.88 67.56,40.89 B07.J2 | v43.43,62.74 61.47,80.77 91.44,80.77 94.49,83.82 98.04,83.82 98.04,91.95 99.57,93.47 101.35,93.47 102.62,94.74 A05.P1
  Bottom 0.254: v43.43,62.74 41.66,60.96 41.66,42.67 42.42,41.91 B09.J2
BINIT  (via drill 0.61)
  Top 0.254: v100.84,76.71 102.36,75.18 143.26,75.18 144.27,76.2 144.27,78.74 A01.V2
  Bottom 0.254: B01.V2 144.78,10.16 145.8,11.18 145.8,77.72 144.78,78.74 A01.V2 | v100.84,76.71 98.3,79.25 98.3,99.57 97.03,100.84 A05.M2
BIOP1  (via drill 0.61)
  Top 0.254: 95.5,24.13 35.05,24.13 34.04,25.15 B10.P2 | 95.5,24.13 96.27,24.89 B05.P2 | 108.2,24.13 108.97,24.89 B04.P2 | 108.2,24.13 95.5,24.13 | 108.2,24.13 135.64,24.13 144.53,33.02 147.32,33.02 147.32,37.34 B01.K2 | v102.62,103.89 103.12,103.38 113.28,103.38 114.05,104.14 114.55,104.14 115.32,103.38 147.32,103.38 147.32,107.19 A01.K2 | v103.12,61.72 106.93,61.72 v108.71,59.94
  Bottom 0.254: v102.62,103.89 101.35,102.62 101.35,77.47 101.85,76.96 101.85,62.99 v103.12,61.72 | v108.71,59.94 108.2,59.44 108.2,45.72 107.7,45.21 107.7,43.69 108.2,43.18 108.2,37.34 110.74,34.8 110.74,27.18 109.73,26.16 B04.P2
BIOP2  (via drill 0.61)
  Top 0.254: B10.R2 30.73,21.84 31.75,20.83 91.95,20.83 92.96,21.84 B05.R2 94.23,22.61 95.25,23.62 104.65,23.62 | 104.65,23.62 105.66,22.61 B04.R2 | v146.81,28.96 141.48,23.62 104.65,23.62 | v103.63,92.2 104.9,93.47 109.73,93.47 110.74,94.49 111.25,94.49 111.76,93.98 136.91,93.98 139.45,96.52 147.32,96.52 147.32,100.84 A01.M2 | v102.87,73.15 99.57,69.85 v87.63,69.85
  Bottom 0.254: v146.81,28.96 146.81,30.48 147.32,30.99 B01.M2 | v103.63,92.2 101.85,90.42 101.85,77.72 102.87,76.71 v102.87,73.15 | v87.63,69.85 86.11,68.33 86.11,31.75 93.22,24.64 93.22,22.86 B05.R2
BIOP4  (via drill 0.61)
  Top 0.254: 95.5,17.78 35.05,17.78 34.04,18.8 B10.S2 | 95.5,17.78 96.27,18.54 B05.S2 | 95.5,17.78 100.08,17.78 | 100.08,17.78 108.2,17.78 108.97,18.54 B04.S2 | 100.08,17.78 103.63,21.34 105.16,21.34 105.66,20.83 147.32,20.83 147.32,24.64 B01.P2 | v147.32,92.46 145.54,90.68 105.41,90.68 104.9,91.19 103.63,91.19 101.35,88.9 101.35,77.72 96.27,77.72 94.23,75.69 v93.98,75.69
  Bottom 0.254: v147.32,92.46 147.32,94.49 A01.P2 | v93.98,75.69 91.95,73.66 91.95,39.88 95.5,36.32 95.5,20.83 96.52,19.81 B05.S2
BMB03\  (via drill 0.61)
  Top 0.254: 91.95,55.37 v63.75,55.37 31.75,55.37 30.73,54.36 B10.D2 | 91.95,55.37 92.96,54.36 B05.D2 | 91.95,55.37 104.65,55.37 105.66,54.36 B04.D2 | v106.43,49.28 106.68,49.02 119.63,49.02 120.4,48.26 121.67,48.26 122.43,49.02 134.37,49.02 137.16,46.23 139.45,46.23 140.72,44.96 B02.H1
  Bottom 0.254: v106.43,49.28 106.43,53.34 B04.D2 | v63.75,55.37 63.75,139.45 137.92,139.45 142.49,134.87 142.49,116.08 141.48,115.06 A02.H1
BMB04\  (via drill 0.61)
  Top 0.254: B10.E2 34.04,50.55 35.05,49.53 95.5,49.53 96.27,50.29 B05.E2 97.54,51.05 98.55,52.07 108.2,52.07 | 108.2,52.07 108.97,51.31 B04.E2 | v137.16,50.8 135.89,52.07 108.2,52.07
  Bottom 0.254: B02.L1 137.67,35.56 136.91,36.32 136.91,50.55 v137.16,50.8 136.91,51.05 136.91,60.96 138.18,62.23 138.18,77.47 136.91,78.74 136.91,89.66 136.4,90.17 136.4,95.5 136.65,95.76 136.65,98.81 137.16,99.31 137.16,103.63 137.67,104.14 A02.L1
BMB05\  (via drill 0.61)
  Top 0.254: B10.F2 30.73,48.01 31.75,49.02 91.95,49.02 92.96,48.01 B05.F2 94.23,48.01 97.03,48.01 98.04,49.02 104.65,49.02 105.66,48.01 B04.F2 | v137.16,32.26 136.4,33.02 131.06,33.02 130.56,33.53 111.51,33.53 109.73,35.31 v108.97,35.31 | v142.24,84.84 142.24,83.31 142.49,83.31 142.49,76.96 v109.98,76.96
  Bottom 0.254: v137.16,32.26 139.45,29.97 139.45,27.69 140.97,26.16 B02.P1 | v108.97,35.31 107.7,36.58 107.7,42.93 106.68,43.94 106.68,46.99 B04.F2 106.68,48.26 107.7,49.28 107.7,63.5 108.46,64.26 108.46,75.44 v109.98,76.96 | v142.24,84.84 142.49,85.09 142.49,93.47 141.48,94.49 A02.P1
BMB06  (via drill 0.61)
  Top 0.254: B10.H2 34.04,44.2 35.05,43.18 95.5,43.18 96.27,43.94 B05.H2 97.54,44.2 98.55,43.18 108.2,43.18 108.97,43.94 B04.H2 110.24,44.45 111,44.45 112.27,45.72 131.83,45.72 v134.11,48.01
  Bottom 0.254: v134.11,48.01 134.11,49.53 134.62,50.04 B02.E2 134.62,51.56 133.6,52.58 133.6,64.01 134.11,64.52 134.11,74.42 133.6,74.93 133.6,118.87 134.62,119.89 A02.E2
BMB07  (via drill 0.61)
  Top 0.254: B10.J2 30.73,41.66 31.75,42.67 91.95,42.67 92.96,41.66 B05.J2 94.23,40.89 95.25,39.88 133.1,39.88 134.37,38.61 B02.K2 | v116.08,106.17 116.59,106.68 133.6,106.68 134.37,107.44 A02.K2 | v112.52,67.82 111.51,66.8 v93.98,66.8
  Bottom 0.254: v116.08,106.17 115.32,105.41 115.32,102.87 114.05,101.6 114.05,69.34 v112.52,67.82 | v93.98,66.8 92.46,65.28 92.46,42.67 93.22,41.91 B05.J2
BMB07\  (via drill 0.61)
  Top 0.254: B04.J2 106.93,41.66 107.44,42.16 111.76,42.16 112.27,42.67 v117.35,42.67 133.1,42.67 134.37,43.94 B02.H2 | v131.57,82.8 126.75,77.98 v117.35,77.98
  Bottom 0.254: v131.57,82.8 133.1,84.33 133.1,121.92 135.64,121.92 136.14,121.41 136.14,116.08 135.13,115.06 A02.H2 | v117.35,77.98 v117.35,42.67
BMB08  (via drill 0.61)
  Top 0.254: 108.2,39.37 35.05,39.37 34.04,38.35 B10.K2 | 108.2,39.37 108.97,38.61 B04.K2 | 108.2,39.37 123.7,39.37 126.24,36.83 139.45,36.83 139.45,32.51 136.91,29.97 135.13,29.97 135.13,26.16 B02.P2 | v135.89,84.84 134.87,83.82 v113.03,83.82
  Bottom 0.254: v135.89,84.84 136.14,85.09 136.14,89.66 135.89,89.92 135.89,93.73 135.13,94.49 A02.P2 | v113.03,83.82 111.51,82.3 111.51,57.15 112.01,56.64 112.01,55.12 110.74,53.85 110.74,47.5 108.2,44.96 108.2,43.94 109.22,42.93 109.22,38.86 B04.K2
BMB08\  (via drill 0.61)
  Top 0.254: v98.3,34.8 100.08,33.02 130.3,33.02 131.06,32.26 134.37,32.26 B02.M2 | v134.62,97.03 134.11,96.52 v119.89,96.52 | v120.4,73.66 119.89,74.17 101.6,74.17 v98.3,70.87
  Bottom 0.254: 98.04,36.32 98.3,36.07 v98.3,34.8 | 98.04,36.32 97.03,37.34 B05.K2 | v134.62,97.03 134.62,100.84 A02.M2 | v119.89,96.52 120.4,96.01 v120.4,73.66 | v98.3,70.87 98.04,70.61 98.04,36.32
BMB10  (via drill 0.61)
  Top 0.254: A06.C1 91.19,127.25 92.2,128.27 114.55,128.27 115.32,127.51 A04.C1 116.59,126.75 118.11,125.22 v126.24,125.22 | v132.08,50.04 132.59,49.53 137.16,49.53 139.45,51.82 139.45,64.26 v137.16,64.26 | v136.4,77.98 136.4,84.07 136.91,84.58 136.91,85.85 132.33,85.85 A02.T2 131.06,86.11 v129.54,87.63
  Bottom 0.254: v132.08,50.04 130.56,48.51 130.56,17.27 131.32,16.51 B02.T2 | v137.16,64.26 136.65,64.77 136.65,77.72 v136.4,77.98 | v126.24,125.22 130.05,121.41 130.05,88.14 v129.54,87.63
BMB11  (via drill 0.61)
  Top 0.254: v87.63,74.68 132.59,74.68 v133.1,74.17
  Bottom 0.254: B02.V2 132.08,10.16 133.1,11.18 v133.1,74.17 133.1,77.72 132.08,78.74 A02.V2 | v87.63,74.68 85.6,76.71 85.6,109.22 86.87,110.49 A06.J1
BR0
  Top 0.254: 15.49,113.54 15.49,107.19 14.99,106.68 6.86,106.68 5.33,105.16 A12.L2 | 15.49,113.54 14.48,113.54 A12.H1 | 15.49,113.54 21.34,119.38 89.15,119.38 89.92,120.14 A06.E1
BR0\  (via drill 0.61)
  Top 0.254: v27.18,118.36 29.97,115.57 76.45,115.57 76.96,116.08 85.6,116.08 86.61,117.09 A06.F1
  Bottom 0.254: v27.18,118.36 25.65,119.89 25.65,124.71 19.3,131.06 19.3,133.1 14.99,133.1 A12.A1
BR1  (via drill 0.61)
  Top 0.254: v87.12,100.08 83.57,96.52 16.76,96.52 11.94,101.35 8.64,101.35 A12.M2
  Bottom 0.254: A12.M2 7.37,102.11 3.56,102.11 3.56,120.65 10.67,127.76 10.67,129.54 A12.B1 | v87.12,100.08 87.12,104.14 A06.L1
BR1\
  Top 0.254: A12.J1 10.67,111.76 10.67,115.57 7.37,115.57 3.56,111.76 3.56,102.87 36.58,102.87 39.62,99.82 85.6,99.82 86.87,101.09 89.92,101.09 A06.M1
BR_CLK  (via drill 0.61)
  Top 0.254: v38.35,102.62 48.26,112.52 85.6,112.52 86.87,113.79 89.92,113.79 A06.H1
  Bottom 0.254: v38.35,102.62 38.35,52.58 39.37,51.56 B10.E1 | A06.B1 87.63,129.54 89.15,128.02 89.15,116.08 90.17,115.06 A06.H1
BRP
  Bottom 0.254: B12.T2 5.08,16.51 6.6,18.03 6.6,80.77 7.62,81.79 A12.U2
CLEARX\
  Bottom 0.254: B04.H1 115.57,45.21 114.55,46.23 114.55,49.02 114.05,49.53 114.05,58.67 113.03,59.69 B04.B1
CLEARY\
  Bottom 0.254: B05.H1 102.87,45.21 101.35,46.74 101.35,56.9 100.33,57.91 100.33,59.69 B05.B1
CLOCKX  (via drill 0.61)
  Top 0.254: v114.05,26.67 70.36,26.67 68.83,28.19 B07.N2
  Bottom 0.254: v114.05,26.67 114.55,27.18 114.55,36.32 115.57,37.34 B04.K1 | A07.D2 67.82,123.19 66.55,121.92 66.55,30.48 67.82,29.21 B07.N2
CLOCKY  (via drill 0.61)
  Top 0.254: v44.45,32 49.28,36.83 101.85,36.83 102.62,37.59 B05.K1
  Bottom 0.254: B09.N2 43.18,29.21 44.45,30.48 v44.45,32 44.2,32.26 44.2,35.56 41.15,38.61 41.15,121.92 42.42,123.19 A09.D2
DELAYP\
  Top 0.254: B11.S2 20.32,19.81 20.32,24.13 20.07,24.13 3.56,40.64 3.56,85.34 4.06,85.34 A12.T2
DISPLAY
  Top 0.254: B12.H2 8.64,44.2 9.65,43.18 19.3,43.18 20.07,43.94 B11.H2 21.34,44.2 22.86,44.2 36.58,30.48 106.43,30.48 107.44,29.46 111.51,29.46 112.01,28.96 B04.N1
DISPP
  Top 0.254: A05.T2 92.96,86.11 91.95,87.12 30.73,87.12 27.18,90.68 6.35,90.68 5.33,91.69 A12.R2
  Bottom 0.254: 12.45,101.09 13.72,101.09 A12.M1 | 12.45,101.09 11.94,101.09 6.6,95.76 6.6,94.23 5.08,92.71 A12.R2 | 12.45,101.09 12.45,120.4 8.64,120.4 A12.E2
DISPP\
  Top 0.254: A12.V2 5.08,80.01 5.08,83.82 93.73,83.82 96.52,86.61 96.52,88.14 A05.S2
DISX\
  Bottom 0.254: B04.L1 112.27,35.56 111.51,36.32 111.51,44.96 112.27,45.72 112.27,46.99 B04.F1
DISY\  (via drill 0.61)
  Top 0.254: v110.74,45.47 109.98,46.23 101.6,46.23 100.58,47.24 B05.F1
  Bottom 0.254: v110.74,45.47 110.74,36.32 111.25,35.81 111.25,25.65 114.3,25.65 115.06,26.42 115.06,30.48 115.57,30.99 B04.M1
INIT\
  Bottom 0.254: A05.N2 93.22,99.06 91.69,100.58 91.69,106.17 90.68,107.19 A06.K1 90.42,108.71 90.42,111 88.65,112.78 88.65,122.17 87.63,123.19 A06.D1
INT1
  Top 0.254: A12.D2 5.08,123.19 5.08,118.87 9.4,118.87 10.41,117.86 A12.F1
INT1\
  Top 0.254: A12.E1 13.72,121.16 13.46,121.16 11.43,123.19 A12.D1 11.68,124.21 11.94,124.21 13.97,126.24 A12.C1
INT1P\
  Bottom 0.254: A11.P1 26.67,96.01 25.15,97.54 25.15,124.46 24.38,125.22 8.89,125.22 8.89,123.44 5.08,119.63 5.08,118.11 A12.F2
INT2
  Bottom 0.254: A12.L1 10.41,105.16 8.38,107.19 8.38,107.44 A12.K2
INT2\
  Top 0.254: 7.11,113.28 7.37,113.54 7.62,113.54 A12.H2 | 7.11,113.28 5.33,111.51 A12.J2 | 7.11,113.28 10.67,109.73 12.45,109.73 13.72,108.46 A12.K1
INT2P\
  Top 0.254: A12.N1 11.68,98.04 13.21,96.52 16,96.52 20.07,92.46 23.11,92.46 A11.R1
INT3
  Bottom 0.254: A12.S1 13.72,89.41 9.14,89.41 9.14,93.47 8.13,94.49 A12.P2
INT3\
  Top 0.254: A12.N2 5.33,98.04 6.86,96.52 12.45,96.52 13.21,95.76 13.72,95.76 A12.P1 13.97,94.49 13.72,94.49 11.68,92.46 A12.R1
INT3P\
  Top 0.254: A12.S2 8.64,88.65 9.65,87.63 25.65,87.63 26.42,88.39 A11.S1
LOADX\
  Bottom 0.254: B04.J1 113.03,41.91 114.05,42.93 114.05,48.77 113.03,49.78 113.03,53.34 B04.D1
LOADY\
  Bottom 0.254: B05.J1 99.57,41.91 98.81,42.67 98.81,52.58 99.57,53.34 B05.D1
N$1
  Bottom 0.254: A05.R2 93.98,92.71 95,93.73 95,107.95 91.69,111.25 91.69,131.57 90.68,132.59 A06.A1
N$2
  Top 0.254: B11.J2 17.78,40.64 19.81,38.61 20.07,38.61 B11.K2
N$4
  Top 0.254: B12.J2 5.08,40.64 7.11,38.61 7.37,38.61 B12.K2
N$6
  Top 0.254: B11.D2 17.78,53.34 19.81,51.31 20.07,51.31 B11.E2
N$7
  Top 0.254: B12.D2 5.08,53.34 7.11,51.31 7.37,51.31 B12.E2
N$9
  Top 0.254: A05.A1 103.89,133.1 105.41,131.57 111,131.57 112.01,130.56 A04.B1
N$10
  Top 0.254: A05.C1 103.89,126.75 105.41,125.22 109.47,125.22 113.54,121.16 115.32,121.16 A04.E1
N$11
  Bottom 0.254: A04.F2 105.66,117.86 101.35,117.86 101.35,122.17 100.33,123.19 A05.D1
N$12
  Top 0.254: A05.F1 100.58,117.09 102.11,115.57 114.05,115.57 114.81,114.81 115.32,114.81 A04.H1
N$13
  Bottom 0.254: A04.J2 105.66,111.51 102.87,111.51 102.87,112.78 97.03,118.62 97.03,119.89 A05.E2
N$14
  Top 0.254: A05.N1 100.58,98.04 102.11,96.52 114.55,96.52 115.32,95.76 A04.P1
N$15  (via drill 0.61)
  Top 0.254: v98.55,101.85 101.09,99.31 105.16,99.31 105.66,98.81 A04.N2
  Bottom 0.254: v98.55,101.85 97.03,103.38 97.03,107.19 A05.K2
N$16
  Top 0.254: A05.L1 100.58,104.39 102.11,102.87 113.28,102.87 114.05,102.11 115.32,102.11 A04.M1
N$17
  Bottom 0.254: A04.L2 105.92,105.41 105.92,107.7 99.57,114.05 97.54,114.05 A05.H2
N$18  (via drill 0.61)
  Top 0.254: v101.85,106.17 102.11,106.43 114.3,106.43 115.32,107.44 A04.K1
  Bottom 0.254: v101.85,106.17 101.85,108.97 100.33,110.49 A05.J1
N$21  (via drill 0.61)
  Top 0.254: v100.33,64.77 103.89,64.77 106.43,62.23 123.19,62.23 124.71,60.71 B03.B1
  Bottom 0.254: v100.33,64.77 99.31,65.79 99.31,76.2 95.5,80.01 95.5,110.49 95,111 95,121.92 104.65,131.57 124.97,131.57 124.97,130.81 A03.B1
N$22  (via drill 0.61)
  Top 0.254: v101.6,57.91 102.11,58.42 111.51,58.42 114.55,55.37 123.7,55.37 124.71,54.36 B03.D1 | v97.28,80.77 98.81,82.3 98.81,90.68 100.84,90.68 v105.66,95.5
  Bottom 0.254: v101.6,57.91 101.35,58.17 101.35,74.93 97.28,78.99 v97.28,80.77 | v105.66,95.5 108.2,98.04 108.2,122.43 114.55,128.78 121.41,128.78 121.41,129.03 122.17,129.79 124.21,129.79 124.21,127.76 124.97,127 124.97,124.46 A03.D1
N$23
  Bottom 0.254: B03.E1 128.27,51.56 127.25,52.58 127.25,118.87 128.27,119.89 A03.E1
N$24  (via drill 0.61)
  Top 0.254: v96.27,42.67 108.46,42.67 108.97,43.18 116.59,43.18 117.35,43.94 118.62,43.94 119.38,43.18 127.25,43.18 128.02,43.94 B03.H1 | v93.47,45.47 92.96,45.97 v80.77,45.97 | v84.58,122.94 85.09,122.43 109.47,122.43 v110.24,123.19 | v123.7,113.54 123.95,113.79 128.02,113.79 A03.H1
  Bottom 0.254: v93.47,45.47 v96.27,42.67 | v80.77,45.97 79.76,46.99 79.76,118.11 v84.58,122.94 | v110.24,123.19 112.27,125.22 123.7,125.22 v123.7,113.54
N$26
  Bottom 0.254: B03.J1 125.73,41.91 126.75,42.93 126.75,109.47 125.73,110.49 A03.J1
N$27
  Bottom 0.254: B03.L1 125.48,35.56 125.48,39.37 124.21,40.64 124.21,103.38 124.97,104.14 A03.L1
N$28  (via drill 0.61)
  Top 0.254: v84.58,35.81 85.09,36.32 113.28,36.32 114.3,35.31 117.35,35.31 118.36,36.32 128.52,36.32 131.32,33.53 138.18,33.53 138.18,32 136.65,30.48 130.3,30.48 129.29,31.5 B03.M1 | v82.3,113.54 82.8,113.03 85.34,113.03 87.38,115.06 89.41,115.06 90.42,116.08 96.77,116.08 102.62,121.92 112.01,121.92 114.55,119.38 118.36,119.38 v118.87,119.89 | v119.89,101.85 121.41,100.33 127.25,100.33 128.02,101.09 A03.M1
  Bottom 0.254: v84.58,35.81 82.3,38.1 v82.3,113.54 | v118.87,119.89 120.4,118.36 120.4,102.36 v119.89,101.85
N$29  (via drill 0.61)
  Top 0.254: v126.75,27.69 126.24,27.18 118.11,27.18 117.6,27.69 113.79,27.69 113.28,27.18 93.22,27.18 v91.69,28.7 | v135.64,98.81 134.87,98.04 133.35,98.04 132.33,97.03 129.54,97.03 v129.03,97.54
  Bottom 0.254: v126.75,27.69 128.27,26.16 B03.P1 | v91.69,28.7 91.69,39.37 88.65,42.42 88.65,72.39 82.8,78.23 82.8,111 86.11,114.3 86.11,130.81 89.92,134.62 136.4,134.62 136.4,121.92 136.65,121.67 136.65,99.82 v135.64,98.81 | v129.03,97.54 128.78,97.28 128.78,96.01 A03.P1
N$30
  Bottom 0.254: B03.S1 128.78,19.81 129.79,20.83 129.79,86.11 128.52,87.38 128.52,88.14 A03.S1
N$33
  Bottom 0.254: B03.D2 118.62,54.61 117.86,55.37 117.86,77.22 118.36,77.72 118.36,78.23 117.6,78.99 117.6,110.49 117.86,110.74 117.86,122.43 118.62,123.19 A03.D2
N$34
  Bottom 0.254: B03.E2 121.92,51.56 120.9,52.58 120.9,72.9 121.41,73.41 121.41,81.53 120.9,82.04 120.9,118.87 121.92,119.89 A03.E2
N$35  (via drill 0.61)
  Top 0.254: v121.41,49.28 121.16,49.53 107.44,49.53 106.68,50.29 104.65,50.29 103.89,49.53 97.28,49.53 v96.77,49.02 | v89.15,104.39 93.98,109.22 113.79,109.22 118.36,113.79 121.67,113.79 A03.H2
  Bottom 0.254: v121.41,49.28 122.43,48.26 122.43,45.21 B03.H2 | v96.77,49.02 95,50.8 95,88.9 89.15,94.74 v89.15,104.39
N$36  (via drill 0.61)
  Top 0.254: v124.46,37.34 123.44,37.34 122.94,37.85 B03.K2 | v69.6,122.94 78.23,131.57 103.12,131.57 105.92,128.78 v122.43,128.78
  Bottom 0.254: v124.46,37.34 123.95,36.83 123.95,11.68 119.89,7.62 72.64,7.62 72.64,47.75 67.06,53.34 67.06,82.55 69.6,85.09 v69.6,122.94 | v122.43,128.78 124.21,127 124.21,116.08 125.48,114.81 125.48,113.03 122.94,110.49 122.94,108.2 A03.K2
N$37  (via drill 0.61)
  Top 0.254: v121.41,46.74 120.9,46.23 118.11,46.23 v116.33,48.01 | v116.59,85.09 119.13,87.63 v123.19,87.63
  Bottom 0.254: v121.41,46.74 120.9,46.23 120.9,33.53 121.92,32.51 B03.M2 | v116.33,48.01 114.55,49.78 114.55,64.52 116.33,66.29 116.33,81.03 117.09,81.79 117.09,84.58 v116.59,85.09 | v123.19,87.63 123.44,87.88 123.44,99.82 122.43,100.84 A03.M2
N$38  (via drill 0.61)
  Top 0.254: v75.95,92.96 76.96,93.98 85.34,93.98 94.23,102.87 100.08,102.87 103.12,99.82 108.2,99.82 111,97.03 118.11,97.03 119.63,95.5 121.67,95.5 A03.P2
  Bottom 0.254: v75.95,92.96 75.95,38.1 82.8,31.24 82.8,8.13 119.63,8.13 120.9,9.4 120.9,23.62 121.92,24.64 B03.P2
N$39
  Bottom 0.254: B03.S2 122.43,19.81 123.44,20.83 123.44,86.11 122.17,87.38 122.17,88.14 A03.S2
N$40  (via drill 0.61)
  Top 0.254: v106.93,76.2 108.71,77.98 114.3,77.98 v118.62,82.3
  Bottom 0.254: v106.93,76.2 105.16,74.42 105.16,27.94 107.7,25.4 107.7,11.43 110.24,11.43 114.05,15.24 114.05,15.49 118.36,15.49 B03.T2 | v118.62,82.3 118.62,85.09 A03.T2
N$41
  Bottom 0.254: B03.V2 119.38,10.16 120.4,11.18 120.4,72.39 119.38,73.41 119.38,78.74 A03.V2
N$42
  Bottom 0.254: B02.D2 131.32,54.61 130.56,55.37 130.56,122.43 131.32,123.19 A02.D2
N$43
  Bottom 0.254: B02.S1 141.48,19.81 142.49,20.83 142.49,75.95 142.24,76.2 142.24,81.53 142.49,81.79 142.49,83.31 141.22,84.58 141.22,88.14 A02.S1
N$44  (via drill 0.61)
  Top 0.254: v137.92,56.13 129.29,64.77 114.05,64.77 v113.54,64.26 | v116.84,111 118.36,112.52 136.4,112.52 137.41,111.51 A02.J1
  Bottom 0.254: v137.92,56.13 139.45,54.61 139.45,42.93 138.43,41.91 B02.J1 | v113.54,64.26 114.55,65.28 114.55,98.3 117.09,100.84 117.09,110.74 v116.84,111
N$45  (via drill 0.61)
  Top 0.254: v138.94,100.84 139.19,101.09 140.72,101.09 A02.M1
  Bottom 0.254: v138.94,100.84 139.45,100.33 139.45,81.79 140.21,81.03 140.21,66.55 139.45,65.79 139.45,56.39 139.95,55.88 139.95,33.53 140.97,32.51 B02.M1
N$46
  Bottom 0.254: B02.S2 135.13,19.81 136.14,20.83 136.14,76.96 135.38,77.72 135.38,81.03 136.14,81.79 136.14,83.31 134.87,84.58 134.87,88.14 A02.S2
N$47  (via drill 0.61)
  Top 0.254: v139.19,66.8 137.16,68.83 79.5,68.83 v70.1,78.23
  Bottom 0.254: v139.19,66.8 138.94,66.55 138.94,61.47 138.43,60.96 B02.B1 | v70.1,78.23 70.1,121.16 87.88,138.94 137.67,138.94 137.67,130.81 A02.B1
N$48  (via drill 0.61)
  Top 0.254: v73.91,70.61 85.6,58.93 112.27,58.93 115.32,55.88 135.89,55.88 137.41,54.36 B02.D1
  Bottom 0.254: v73.91,70.61 73.41,71.12 73.41,107.95 76.45,111 76.45,123.7 91.19,138.43 136.91,138.43 136.91,125.22 137.67,124.46 A02.D1
N$49
  Bottom 0.254: B02.E1 140.97,51.56 140.46,52.07 140.46,56.13 139.95,56.64 139.95,65.53 140.72,66.29 140.72,81.28 139.95,82.04 139.95,118.87 140.97,119.89 A02.E1
N$50  (via drill 0.61)
  Top 0.254: v152.15,40.39 152.15,49.02 151.13,49.02 150.11,50.04 150.11,51.31 150.88,51.31 152.65,53.09 152.65,84.33 146.05,84.33 145.03,85.34 A01.T2
  Bottom 0.254: v152.15,40.39 152.15,8.13 144.02,8.13 143.26,8.89 143.26,14.48 144.02,15.24 B01.T2
N$51
  Bottom 0.254: B01.S2 147.83,19.81 148.84,20.83 148.84,86.11 147.57,87.38 147.57,88.14 A01.S2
